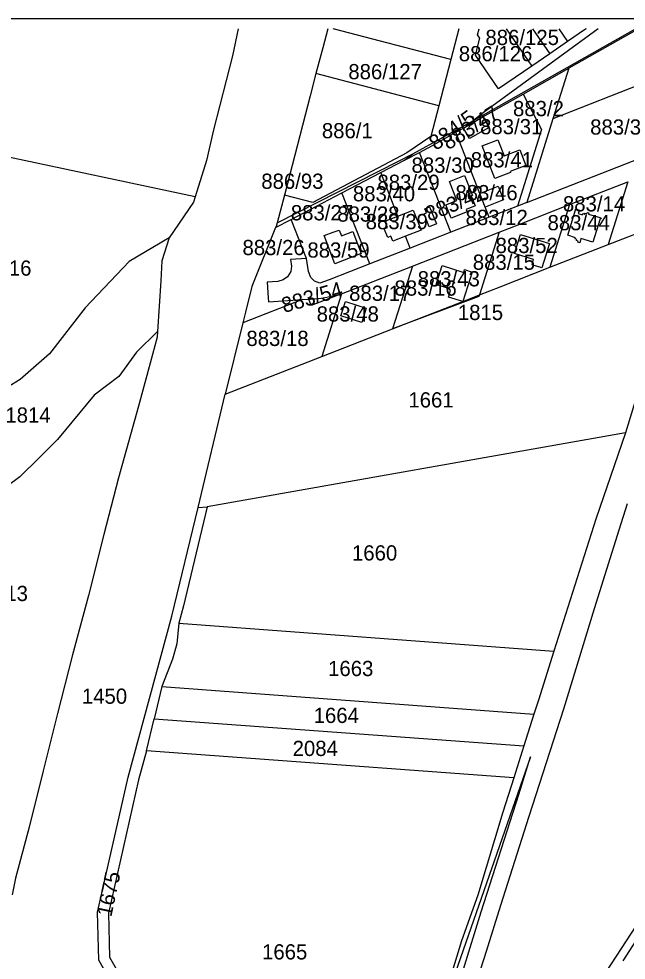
# Model space of a CAD drawing. Extents: x -583889 to -582839, y -1166553 to -1165068.
# Drawn here: x -583391.3 to -583111.8, y -1165500.8 to -1165067.8 of the extents above; entities that cross this region are included whole.
import ezdxf

# ---------------------------------------------------------------- set-up
doc = ezdxf.new("R2010")
doc.units = 0
for name, color, linetype in [('03_PC_NÁVRH', 7, 'Continuous'), ('_parcely přehledka', 7, 'Continuous'), ('Hranice parcel', 7, 'Continuous'), ('Parcelní čísla', 7, 'Continuous')]:
    doc.layers.add(name, color=color, linetype=linetype)

msp = doc.modelspace()

# ---------------------------------------------------------------- linework, layer by layer
at = {"layer": '03_PC_NÁVRH'}
msp.add_lwpolyline([(-583197.54, -1165526.98), (-583193.3, -1165528.49), (-583186.64, -1165505.02), (-583178.54, -1165478.54), (-583161.21, -1165424.69), (-583155.91, -1165407.33), (-583155.91, -1165407.33)], close=True, dxfattribs=at)
at = {"layer": '_parcely přehledka'}
msp.add_lwpolyline([(-583888.67, -1166552.78), (-582838.67, -1166552.78), (-582838.67, -1165067.78), (-583888.67, -1165067.78), (-583888.67, -1166552.78)], dxfattribs=at)
at = {"layer": 'Hranice parcel'}
for p, q in [((-583192.52, -1165086.48), (-583246.64, -1165072.33)), ((-583188.82, -1165072.33), (-583192.52, -1165086.48)), ((-583182.09, -1165114.62), (-583107.53, -1165072.33)), ((-583167.06, -1165072.33), (-583155.29, -1165089.5)), ((-583154.94, -1165072.33), (-583147.04, -1165083.85)), ((-583142.81, -1165072.33), (-583138.79, -1165078.2)), ((-583130.54, -1165072.55), (-583138.79, -1165078.2)), ((-583106.15, -1165072.33), (-583138.25, -1165090.53)), ((-583130.69, -1165072.33), (-583130.54, -1165072.55)), ((-583130.22, -1165072.33), (-583130.54, -1165072.55)), ((-583138.79, -1165078.2), (-583147.04, -1165083.85)), ((-583060.04, -1165080.27), (-583145.52, -1165113.73)), ((-583147.04, -1165083.85), (-583155.29, -1165089.5)), ((-583192.52, -1165086.48), (-583198.08, -1165107.77)), ((-583198.08, -1165107.77), (-583254.56, -1165093)), ((-583159.2, -1165102.41), (-583138.25, -1165090.53)), ((-583138.25, -1165090.53), (-583145.52, -1165113.73)), ((-583177.74, -1165112.93), (-583159.2, -1165102.41)), ((-583209.97, -1165129.86), (-583182.09, -1165114.62)), ((-583185.39, -1165117.27), (-583177.74, -1165112.93)), ((-583182.09, -1165114.62), (-583185.39, -1165117.27)), ((-583145.52, -1165113.73), (-583157.61, -1165152.25)), ((-583190.15, -1165119.97), (-583186.69, -1165118.01)), ((-583179.13, -1165148.17), (-583190.15, -1165119.97)), ((-583186.69, -1165118.01), (-583185.39, -1165117.27)), ((-583157.61, -1165152.25), (-583071.94, -1165118.73)), ((-583310.2, -1165149.72), (-583419.03, -1165126.58)), ((-583213.82, -1165132.82), (-583206.95, -1165129.23)), ((-583192.59, -1165165.93), (-583206.95, -1165129.23)), ((-583224.78, -1165138.54), (-583213.82, -1165132.82)), ((-583213.82, -1165132.82), (-583209.97, -1165129.86)), ((-583242.61, -1165147.85), (-583224.78, -1165138.54)), ((-583216.94, -1165158.58), (-583224.78, -1165138.54)), ((-583137.89, -1165153.24), (-583111.02, -1165142.73)), ((-583111.02, -1165142.73), (-583120.08, -1165171.59)), ((-583269.11, -1165148.86), (-583272.42, -1165161.67)), ((-583266.01, -1165160.07), (-583242.61, -1165147.85)), ((-583229.84, -1165180.5), (-583242.61, -1165147.85)), ((-583176.72, -1165154.36), (-583179.13, -1165148.17)), ((-583174.9, -1165159.01), (-583176.72, -1165154.36)), ((-583161.79, -1165153.89), (-583174.9, -1165159.01)), ((-583157.61, -1165152.25), (-583161.79, -1165153.89)), ((-583137.89, -1165153.24), (-583146.95, -1165182.1)), ((-583174.9, -1165159.01), (-583192.59, -1165165.93)), ((-583120.08, -1165171.59), (-583084.11, -1165157.51)), ((-583273.25, -1165163.85), (-583266.01, -1165160.07)), ((-583258.98, -1165178.07), (-583266.01, -1165160.07)), ((-583211.22, -1165173.22), (-583213.34, -1165167.8)), ((-583192.59, -1165165.93), (-583211.22, -1165173.22)), ((-583210.23, -1165181.54), (-583170.28, -1165165.91)), ((-583170.28, -1165165.91), (-583179.34, -1165194.77)), ((-583146.95, -1165182.1), (-583120.08, -1165171.59)), ((-583211.22, -1165173.22), (-583229.84, -1165180.5)), ((-583242.78, -1165194.27), (-583210.23, -1165181.54)), ((-583210.23, -1165181.54), (-583219.29, -1165210.4)), ((-583242.78, -1165194.27), (-583251.84, -1165223.13)), ((-583260.77, -1165196.96), (-583288.23, -1165207.7)), ((-583260.77, -1165196.96), (-583257.89, -1165196.79)), ((-583288.23, -1165207.7), (-583296.29, -1165240.52)), ((-583251.84, -1165223.13), (-583219.29, -1165210.4)), ((-583296.29, -1165240.52), (-583251.84, -1165223.13)), ((-583308.83, -1165292.52), (-583296.29, -1165240.52)), ((-583112.09, -1165258.27), (-583304.62, -1165292.26)), ((-583308.83, -1165292.52), (-583304.62, -1165292.26)), ((-583317.66, -1165345.79), (-583145.07, -1165358.62)), ((-583325.5, -1165374.92), (-583329.03, -1165389.78)), ((-583325.5, -1165374.92), (-583154.3, -1165387.67)), ((-583154.3, -1165387.67), (-583158.9, -1165402.17)), ((-583332.55, -1165404.6), (-583329.03, -1165389.78)), ((-583329.03, -1165389.78), (-583158.9, -1165402.17)), ((-583158.9, -1165402.17), (-583163.57, -1165416.9)), ((-583163.57, -1165416.9), (-583332.55, -1165404.6))]:
    msp.add_line(p, q, dxfattribs=at)
for points in [[(-583290.39, -1165072.33), (-583293.05, -1165084.81), (-583301.65, -1165118.91), (-583304.95, -1165132.91), (-583310.2, -1165149.72)], [(-583249.12, -1165072.33), (-583251.38, -1165081.18), (-583254.56, -1165093)], [(-583124.73, -1165072.33), (-583177.59, -1165111.01), (-583182.09, -1165114.62)], [(-583155.29, -1165089.5), (-583170.56, -1165099.96), (-583181.14, -1165084.5), (-583179.11, -1165076.73), (-583180.24, -1165075.09), (-583179.52, -1165072.33)], [(-583254.56, -1165093), (-583257.31, -1165103.21), (-583269.11, -1165148.86)], [(-583159.2, -1165102.41), (-583150.74, -1165118.66), (-583161.79, -1165153.89)], [(-583198.08, -1165107.77), (-583201.79, -1165121.97), (-583212.74, -1165129.47), (-583256.06, -1165152.27), (-583269.11, -1165148.86)], [(-583177.74, -1165112.93), (-583174.94, -1165117.84), (-583183.93, -1165122.9), (-583186.69, -1165118.01)], [(-583206.95, -1165129.23), (-583201, -1165126.12), (-583190.15, -1165119.97)], [(-583178.04, -1165126.19), (-583170.85, -1165123.38), (-583167.95, -1165130.86), (-583160.8, -1165128.06), (-583158.01, -1165135.2), (-583165.21, -1165138.06), (-583165.03, -1165138.53), (-583172.2, -1165141.29), (-583178.04, -1165126.19)], [(-583272.42, -1165161.67), (-583216.55, -1165133.21), (-583209.97, -1165129.86)], [(-583194.84, -1165153.37), (-583189.72, -1165151.36), (-583193.17, -1165142.57), (-583186.16, -1165139.84), (-583182.54, -1165149.06), (-583183.1, -1165149.27), (-583181.31, -1165153.85), (-583185.41, -1165155.45), (-583184.97, -1165156.57), (-583192.44, -1165159.48), (-583194.84, -1165153.37)], [(-583179.13, -1165148.17), (-583170.78, -1165144.83), (-583168.3, -1165151), (-583176.72, -1165154.36)], [(-583310.2, -1165149.72), (-583310.93, -1165152.06), (-583322.15, -1165168.47)], [(-583202.27, -1165154.28), (-583199.18, -1165162.12), (-583202.45, -1165163.41), (-583204.81, -1165157.44), (-583203.78, -1165157.04), (-583204.52, -1165155.17), (-583202.27, -1165154.28)], [(-583170.28, -1165165.91), (-583160.72, -1165162.17), (-583137.89, -1165153.24)], [(-583135.17, -1165168.49), (-583138.74, -1165167.33), (-583135, -1165155.19), (-583133.37, -1165155.73), (-583133.88, -1165157.4), (-583131.93, -1165157.97), (-583131.75, -1165157.37), (-583130.94, -1165157.65), (-583130.79, -1165157.12), (-583129.97, -1165157.39), (-583129.81, -1165156.86), (-583128.97, -1165157.1), (-583129.16, -1165157.64), (-583124.03, -1165159.23), (-583123.33, -1165159.47), (-583123.47, -1165159.94), (-583123.86, -1165159.84), (-583127.2, -1165170.5), (-583132.64, -1165168.78), (-583133.2, -1165170.78), (-583134.02, -1165170.52), (-583133.86, -1165170.02), (-583134.66, -1165169.74), (-583134.5, -1165169.23), (-583135.31, -1165168.95), (-583135.17, -1165168.49)], [(-583213.34, -1165167.8), (-583219.24, -1165170.11), (-583220.15, -1165167.79), (-583221.58, -1165168.36), (-583223.16, -1165164.33), (-583221.71, -1165163.77), (-583222.84, -1165160.89), (-583216.94, -1165158.58)], [(-583216.94, -1165158.58), (-583209.83, -1165155.79), (-583206.23, -1165165.02), (-583213.34, -1165167.8)], [(-583273.25, -1165163.85), (-583284.11, -1165190.92), (-583286.96, -1165202.76), (-583288.23, -1165207.7)], [(-583272.42, -1165161.67), (-583272.88, -1165163.39), (-583273.25, -1165163.85)], [(-583250.8, -1165167.53), (-583246.62, -1165165.93), (-583243.85, -1165164.96), (-583242.84, -1165167.68), (-583237.68, -1165165.6), (-583233.77, -1165175.77), (-583245.84, -1165180.42), (-583250.8, -1165167.53)], [(-583154.41, -1165178.52), (-583163.24, -1165175.74), (-583160.51, -1165166.95), (-583147.19, -1165171.14), (-583150.71, -1165182.29), (-583155.13, -1165180.9), (-583154.41, -1165178.52)], [(-583322.15, -1165168.47), (-583340.5, -1165179.46), (-583360.81, -1165200.75), (-583377.25, -1165221.89), (-583390.68, -1165233.74), (-583416.76, -1165249.61), (-583440.61, -1165276.22), (-583445.47, -1165291.1), (-583456.44, -1165295.04)], [(-583322.15, -1165168.47), (-583325.57, -1165179.12), (-583326, -1165188.3), (-583327.43, -1165211.57)], [(-583258.98, -1165178.07), (-583266.29, -1165178.5), (-583265.88, -1165181.52), (-583266.18, -1165183.96), (-583267.73, -1165186.48), (-583269.73, -1165187.92), (-583272.1, -1165188.61), (-583277.05, -1165188.92), (-583276.57, -1165196.2), (-583276.47, -1165197.91), (-583260.77, -1165196.96)], [(-583229.84, -1165180.5), (-583248.47, -1165187.79), (-583252.75, -1165189.46), (-583255.2, -1165188.46), (-583256.97, -1165186.76), (-583258.07, -1165184), (-583258.98, -1165178.07)], [(-583186.95, -1165197.75), (-583193.56, -1165195.75), (-583192.62, -1165192.82), (-583193.18, -1165191.92), (-583199.34, -1165189.93), (-583196.55, -1165181.19), (-583186.6, -1165184.42), (-583186.22, -1165183.15), (-583182.66, -1165184.28), (-583186.95, -1165197.75)], [(-583179.34, -1165194.77), (-583169.78, -1165191.03), (-583146.95, -1165182.1)], [(-583257.89, -1165196.79), (-583257.11, -1165196.74), (-583252.11, -1165196.21), (-583249.62, -1165195.75), (-583242.78, -1165194.27)], [(-583242.78, -1165194.27), (-583256.75, -1165199.73), (-583257.89, -1165196.79)], [(-583241.02, -1165197.83), (-583231.44, -1165200.93), (-583233.47, -1165207.47), (-583243.14, -1165204.44), (-583241.02, -1165197.83)], [(-583219.29, -1165210.4), (-583186.95, -1165197.75), (-583179.34, -1165194.77)], [(-583179.34, -1165194.77), (-583179.66, -1165195.53), (-583219.29, -1165210.4)], [(-583327.43, -1165211.57), (-583337.15, -1165221.16), (-583345.28, -1165232.38), (-583356.63, -1165240.96), (-583373.5, -1165261.36), (-583381.99, -1165269.78), (-583390.9, -1165278.52), (-583409.51, -1165292.26), (-583429.18, -1165300.2), (-583454.83, -1165307.19)], [(-583327.43, -1165211.57), (-583327.59, -1165214.21), (-583330.92, -1165226.21), (-583336.19, -1165245.95), (-583345.5, -1165278.93), (-583352.15, -1165304.95), (-583359.3, -1165333.07), (-583366.57, -1165360.34), (-583373.53, -1165387.37), (-583380.03, -1165413.66), (-583386.52, -1165439.72), (-583392.75, -1165463.03), (-583394.35, -1165470.85)], [(-583097.01, -1165208.5), (-583101.24, -1165222.44), (-583112.09, -1165258.27)], [(-583112.09, -1165258.27), (-583125.85, -1165297.89), (-583145.07, -1165358.62)], [(-583361.04, -1165570.69), (-583342.57, -1165547.76), (-583341.85, -1165530.97), (-583343.72, -1165519.91), (-583354.54, -1165500.86), (-583355.11, -1165478.77), (-583350.44, -1165458.56), (-583341.01, -1165416.67), (-583320.9, -1165342.6), (-583308.83, -1165292.52)], [(-583304.62, -1165292.26), (-583315.52, -1165337.89), (-583317.66, -1165345.79)], [(-583184.72, -1165523.62), (-583182.81, -1165517.68), (-583176.05, -1165496.65), (-583169.59, -1165475.46), (-583156.46, -1165434.65), (-583140.6, -1165385.28), (-583126.45, -1165339.09), (-583115, -1165302.85), (-583111.16, -1165290.82)], [(-583150.03, -1165547.02), (-583146.45, -1165545.26), (-583081.48, -1165445.65), (-583060.78, -1165413.9), (-582999.79, -1165321.21), (-583000.42, -1165318.79)], [(-583317.66, -1165345.79), (-583318.57, -1165355.26), (-583320.51, -1165362.38), (-583325.5, -1165374.92)], [(-583145.07, -1165358.62), (-583152.23, -1165381.21), (-583154.3, -1165387.67)], [(-583332.55, -1165404.6), (-583336.16, -1165417.88), (-583350.1, -1165479.27), (-583349.57, -1165499.48), (-583339.8, -1165516.68), (-583336.86, -1165530.49), (-583338.68, -1165550.89), (-583347.2, -1165561.47), (-583348.01, -1165573.19)], [(-583163.57, -1165416.9), (-583168.61, -1165432.78), (-583180.14, -1165470.95), (-583187.62, -1165491.96), (-583193.05, -1165509.63), (-583194.86, -1165515.1)], [(-583078.55, -1165447.56), (-583104.44, -1165487.27), (-583113.44, -1165501.07)]]:
    msp.add_lwpolyline(points, dxfattribs=at)

# ---------------------------------------------------------------- texts
at = {"layer": 'Parcelní čísla'}
for s, p in [('886/125', (-583176.6, -1165079.83)), ('886/126', (-583188.85, -1165087.31)), ('886/127', (-583239.68, -1165095.58)), ('883/2', (-583163.92, -1165112.56)), ('886/1', (-583251.86, -1165122.73)), ('883/31', (-583179.05, -1165120.88)), ('883/3', (-583128.41, -1165121.04)), ('883/41', (-583183.35, -1165136.11)), ('883/30', (-583210.6, -1165138.6)), ('886/93', (-583279.73, -1165145.99)), ('883/29', (-583226.29, -1165146.48)), ('883/40', (-583237.59, -1165151.74)), ('883/46', (-583190.4, -1165151.24)), ('883/14', (-583140.94, -1165156.38)), ('883/27', (-583266.13, -1165160.49)), ('883/28', (-583244.77, -1165161.09)), ('883/12', (-583185.74, -1165162.64)), ('883/39', (-583231.71, -1165164.56)), ('883/44', (-583148.02, -1165165.05)), ('883/52', (-583171.94, -1165175.53)), ('883/26', (-583288.38, -1165176.48)), ('883/59', (-583258.52, -1165177.63)), ('883/15', (-583182.42, -1165183.23)), ('1816', (-583406.3, -1165185.94)), ('883/43', (-583207.79, -1165190.86)), ('883/16', (-583218.44, -1165195.14)), ('883/17', (-583239.32, -1165197.53)), ('883/48', (-583254.26, -1165207.05)), ('1815', (-583189.29, -1165206.35)), ('883/18', (-583286.58, -1165218.29)), ('1661', (-583212.05, -1165246.58)), ('1814', (-583397.49, -1165253.55)), ('1660', (-583238.01, -1165316.98)), ('1813', (-583407.93, -1165335.62)), ('1663', (-583248.99, -1165370.14)), ('1450', (-583362.28, -1165382.89)), ('1664', (-583255.63, -1165391.72)), ('2084', (-583265.32, -1165406.91)), ('1665', (-583279.38, -1165500.5))]:
    msp.add_text(s, height=7, dxfattribs=at).set_placement(p)
for s, rotation, p in [('883/47', 32, (-583193.77, -1165128.32)), ('884/5', 36, (-583199.35, -1165128.61)), ('883/42', 22, (-583202.48, -1165161.15)), ('883/54', 16, (-583269.24, -1165203.13)), ('1675', 78, (-583348.76, -1165481.23))]:
    msp.add_text(s, height=7, rotation=rotation, dxfattribs=at).set_placement(p)

doc.saveas('drawing.dxf')
